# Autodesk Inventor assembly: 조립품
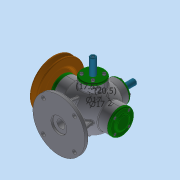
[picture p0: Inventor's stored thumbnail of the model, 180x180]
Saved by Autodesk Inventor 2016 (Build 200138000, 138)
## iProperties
Created: 2019-11
Part Number: 조립품
Material: 일반
Document SubType Name: Assembly
Designer: user
Author: user
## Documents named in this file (17)
- C:\Users\user\Desktop\391120V1006\조립품.iam
- C:\Users\user\Desktop\391120V1006\V-벨트풀리.ipt
- C:\Users\user\Desktop\391120V1006\너트 M8x1.ipt
- C:\Users\user\Desktop\391120V1006\뒤커버.ipt
- C:\Users\user\Desktop\391120V1006\베어링 6202.ipt
- C:\Users\user\Desktop\391120V1006\본체.ipt
- C:\Users\user\Desktop\391120V1006\본체커버.ipt
- C:\Users\user\Desktop\391120V1006\볼트 M4.ipt
- C:\Users\user\Desktop\391120V1006\스프링 1.ipt
- C:\Users\user\Desktop\391120V1006\스프링2.ipt
- C:\Users\user\Desktop\391120V1006\슬라이드 커버.ipt
- C:\Users\user\Desktop\391120V1006\슬라이드.ipt
- C:\Users\user\Desktop\391120V1006\앞커버.ipt
- C:\Users\user\Desktop\391120V1006\오일 실.ipt
- C:\Users\user\Desktop\391120V1006\와셔 8x17.ipt
- C:\Users\user\Desktop\391120V1006\축.ipt
- C:\Users\user\Desktop\391120V1006\키 4x4.ipt
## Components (1 placed, 1 different names)
1. V-벨트풀리:1
